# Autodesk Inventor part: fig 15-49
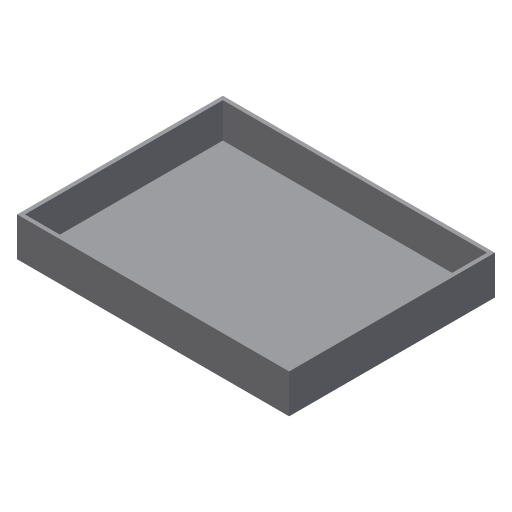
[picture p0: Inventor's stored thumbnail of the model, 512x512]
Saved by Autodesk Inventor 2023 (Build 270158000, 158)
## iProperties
Created: 2002-04
Part Number: fig 15-49
Document SubType Name: Sheet Metal
Density: 1 g/cm^3
Sheet Metal Rule: Default
Material: Generic
Appearance: Default
Control State: 0
Master: False
Checked Out: False
Shininess: 77.0
Angle Display Precision: 2
Document Length Units: 11269
Document Angle Units: 11279
Document Time Units: 11290
Document Mass Units: 11283
Document Length Units Precision: 3
Document Angle Units Precision: 2
Compacted: True
Density: 0.0
Volumn: 0.0
Area: 0.0
PropertySet Name: Model Information
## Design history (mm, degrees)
sketch "Sketch1"
  geometry: L1 (-34, 28)-(36, 28); L2 (36, 28)-(36, -24.941); L3 (36, -24.941)-(-34, -24.941); L4 (-34, -24.941)-(-34, 28)
  constraints: 8 end point, 2 parallel, 1 horizontal, 1 perpendicular
extrude "Extrusion1" new body sketch "Sketch1" distance "d0" = 10; taper "d1" = 0 deg
shell "Shell1" dims "d2" = 1
body "Solid1"
other parameters: "Thickness" = 1, "BendRadius" = 1 (= Thickness), "BendReliefWidth" = 1 (= Thickness), "BendReliefDepth" = 0.5 (= 0.5 x Thickness), "CornerReliefSize" = 4 (= 4 x Thickness), "SeamGap" = 0.01, "MinimumRemnant" = 2 (= 2 x Thickness), "TransitionRadius" = 1 (= BendRadius), "JacobiRadiusSize" = 1 (= Thickness), "GapSize" = 1 (= Thickness)
